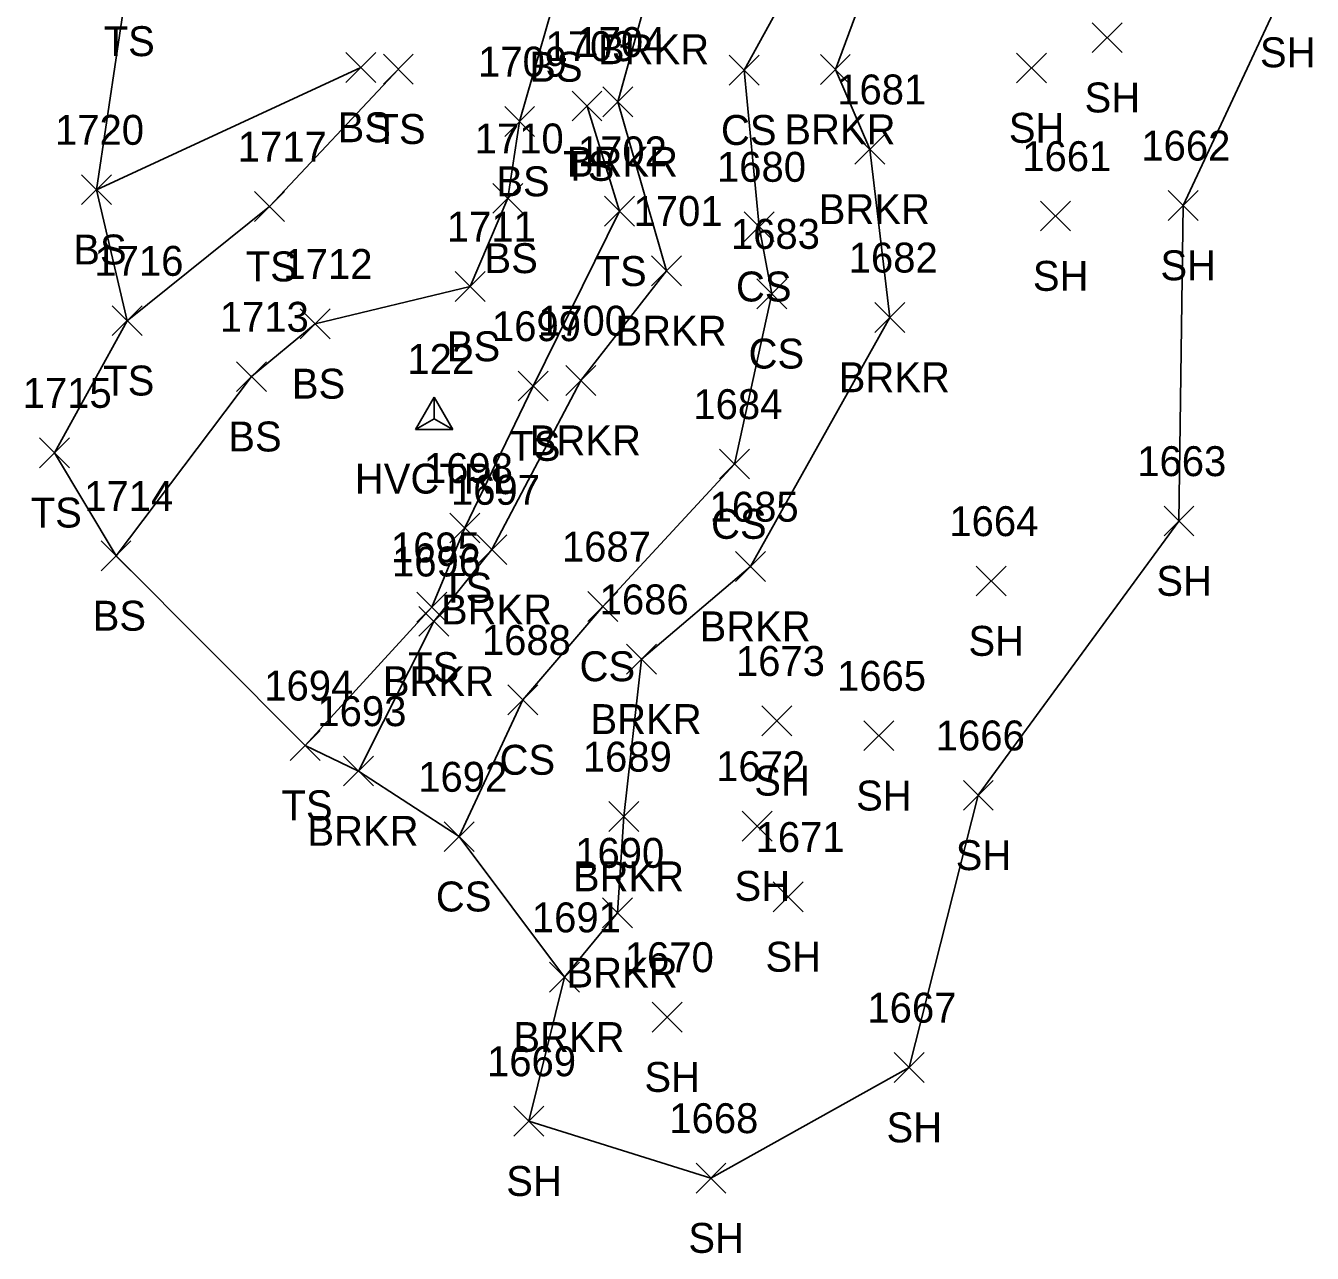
# Model space of a CAD drawing. Extents: x 1526508 to 1531550, y 369926 to 373082.
# Drawn here: x 1530980.2 to 1531066.1, y 369927.2 to 370009.2 of the extents above; entities that cross this region are included whole.
import ezdxf

# ---------------------------------------------------------------- set-up
doc = ezdxf.new("R2010")
doc.units = 0
for name, color, linetype in [('C_A', 7, 'Continuous'), ('C_I', 7, 'Continuous'), ('CPSM', 7, 'Continuous'), ('L_A', 7, 'Continuous'), ('L_I', 7, 'Continuous'), ('L_TIC', 7, 'Continuous'), ('LAWE', 7, 'Continuous'), ('LELB', 7, 'Continuous'), ('LSOGP', 7, 'Continuous')]:
    doc.layers.add(name, color=color, linetype=linetype)

msp = doc.modelspace()

# ---------------------------------------------------------------- linework, layer by layer
at = {"layer": 'CPSM'}
for p, q in [((1531006.222, 369982.223), (1531007.472, 369984.388)), ((1531008.722, 369982.223), (1531007.472, 369984.388)), ((1531007.473, 369982.944), (1531007.472, 369984.388)), ((1531006.222, 369982.223), (1531007.473, 369982.944)), ((1531007.473, 369982.944), (1531007.473, 369982.944)), ((1531007.473, 369982.944), (1531008.722, 369982.223)), ((1531006.222, 369982.223), (1531008.722, 369982.223))]:
    msp.add_line(p, q, dxfattribs=at)
at = {"layer": 'L_TIC'}
for points in [[(1531051.441, 370007.417), (1531053.441, 370009.417)], [(1531053.441, 370007.417), (1531051.441, 370009.417)], [(1531001.569, 370005.428), (1531003.569, 370007.428)], [(1531003.569, 370005.428), (1531001.569, 370007.428)], [(1531004.072, 370005.31), (1531006.072, 370007.31)], [(1531006.072, 370005.31), (1531004.072, 370007.31)], [(1531027.189, 370005.244), (1531029.189, 370007.244)], [(1531029.189, 370005.244), (1531027.189, 370007.244)], [(1531033.276, 370005.285), (1531035.276, 370007.285)], [(1531035.276, 370005.285), (1531033.276, 370007.285)], [(1531046.38, 370005.389), (1531048.38, 370007.389)], [(1531048.38, 370005.389), (1531046.38, 370007.389)], [(1531018.739, 370003.121), (1531020.739, 370005.121)], [(1531020.739, 370003.121), (1531018.739, 370005.121)], [(1531016.68, 370002.846), (1531018.68, 370004.846)], [(1531018.68, 370002.846), (1531016.68, 370004.846)], [(1531012.178, 370001.812), (1531014.178, 370003.812)], [(1531014.178, 370001.812), (1531012.178, 370003.812)], [(1531035.574, 369999.952), (1531037.574, 370001.952)], [(1531037.574, 369999.952), (1531035.574, 370001.952)], [(1530983.907, 369997.254), (1530985.907, 369999.254)], [(1530985.907, 369997.254), (1530983.907, 369999.254)], [(1531011.386, 369996.677), (1531013.386, 369998.677)], [(1531013.386, 369996.677), (1531011.386, 369998.677)], [(1531056.51, 369996.199), (1531058.51, 369998.199)], [(1531058.51, 369996.199), (1531056.51, 369998.199)], [(1530995.465, 369996.124), (1530997.465, 369998.124)], [(1530997.465, 369996.124), (1530995.465, 369998.124)], [(1531018.843, 369995.815), (1531020.843, 369997.815)], [(1531020.843, 369995.815), (1531018.843, 369997.815)], [(1531047.987, 369995.494), (1531049.987, 369997.494)], [(1531049.987, 369995.494), (1531047.987, 369997.494)], [(1531028.192, 369994.782), (1531030.192, 369996.782)], [(1531030.192, 369994.782), (1531028.192, 369996.782)], [(1531021.995, 369991.828), (1531023.995, 369993.828)], [(1531023.995, 369991.828), (1531021.995, 369993.828)], [(1531008.872, 369990.787), (1531010.872, 369992.787)], [(1531010.872, 369990.787), (1531008.872, 369992.787)], [(1531029.035, 369990.3), (1531031.035, 369992.3)], [(1531031.035, 369990.3), (1531029.035, 369992.3)], [(1530985.942, 369988.497), (1530987.942, 369990.497)], [(1530987.942, 369988.497), (1530985.942, 369990.497)], [(1531036.909, 369988.716), (1531038.909, 369990.716)], [(1531038.909, 369988.716), (1531036.909, 369990.716)], [(1530998.516, 369988.286), (1531000.516, 369990.286)], [(1531000.516, 369988.286), (1530998.516, 369990.286)], [(1530994.267, 369984.757), (1530996.267, 369986.757)], [(1530996.267, 369984.757), (1530994.267, 369986.757)], [(1531013.077, 369984.131), (1531015.077, 369986.131)], [(1531015.077, 369984.131), (1531013.077, 369986.131)], [(1531016.264, 369984.498), (1531018.264, 369986.498)], [(1531018.264, 369984.498), (1531016.264, 369986.498)], [(1530981.094, 369979.673), (1530983.094, 369981.673)], [(1530983.094, 369979.673), (1530981.094, 369981.673)], [(1531026.529, 369978.919), (1531028.529, 369980.919)], [(1531028.529, 369978.919), (1531026.529, 369980.919)], [(1531056.238, 369975.108), (1531058.238, 369977.108)], [(1531058.238, 369975.108), (1531056.238, 369977.108)], [(1531008.521, 369974.644), (1531010.521, 369976.644)], [(1531010.521, 369974.644), (1531008.521, 369976.644)], [(1531010.329, 369973.195), (1531012.329, 369975.195)], [(1531012.329, 369973.195), (1531010.329, 369975.195)], [(1530985.205, 369972.777), (1530987.205, 369974.777)], [(1530987.205, 369972.777), (1530985.205, 369974.777)], [(1531027.612, 369972.066), (1531029.612, 369974.066)], [(1531029.612, 369972.066), (1531027.612, 369974.066)], [(1531043.681, 369971.098), (1531045.681, 369973.098)], [(1531045.681, 369971.098), (1531043.681, 369973.098)], [(1531006.316, 369969.342), (1531008.316, 369971.342)], [(1531008.316, 369969.342), (1531006.316, 369971.342)], [(1531017.741, 369969.401), (1531019.741, 369971.401)], [(1531019.741, 369969.401), (1531017.741, 369971.401)], [(1531006.446, 369968.402), (1531008.446, 369970.402)], [(1531008.446, 369968.402), (1531006.446, 369970.402)], [(1531020.32, 369965.868), (1531022.32, 369967.868)], [(1531022.32, 369965.868), (1531020.32, 369967.868)], [(1531012.395, 369963.149), (1531014.395, 369965.149)], [(1531014.395, 369963.149), (1531012.395, 369965.149)], [(1531029.369, 369961.755), (1531031.369, 369963.755)], [(1531031.369, 369961.755), (1531029.369, 369963.755)], [(1530997.854, 369960.108), (1530999.854, 369962.108)], [(1530999.854, 369960.108), (1530997.854, 369962.108)], [(1531036.174, 369960.759), (1531038.174, 369962.759)], [(1531038.174, 369960.759), (1531036.174, 369962.759)], [(1531001.404, 369958.398), (1531003.404, 369960.398)], [(1531003.404, 369958.398), (1531001.404, 369960.398)], [(1531042.829, 369956.774), (1531044.829, 369958.774)], [(1531044.829, 369956.774), (1531042.829, 369958.774)], [(1531019.147, 369955.358), (1531021.147, 369957.358)], [(1531021.147, 369955.358), (1531019.147, 369957.358)], [(1531028.049, 369954.72), (1531030.049, 369956.72)], [(1531030.049, 369954.72), (1531028.049, 369956.72)], [(1531008.139, 369954.011), (1531010.139, 369956.011)], [(1531010.139, 369954.011), (1531008.139, 369956.011)], [(1531030.119, 369949.985), (1531032.119, 369951.985)], [(1531032.119, 369949.985), (1531030.119, 369951.985)], [(1531018.718, 369948.927), (1531020.718, 369950.927)], [(1531020.718, 369948.927), (1531018.718, 369950.927)], [(1531015.167, 369944.616), (1531017.167, 369946.616)], [(1531017.167, 369944.616), (1531015.167, 369946.616)], [(1531022.03, 369941.953), (1531024.03, 369943.953)], [(1531024.03, 369941.953), (1531022.03, 369943.953)], [(1531038.207, 369938.58), (1531040.207, 369940.58)], [(1531040.207, 369938.58), (1531038.207, 369940.58)], [(1531012.795, 369934.997), (1531014.795, 369936.997)], [(1531014.795, 369934.997), (1531012.795, 369936.997)], [(1531024.965, 369931.193), (1531026.965, 369933.193)], [(1531026.965, 369931.193), (1531024.965, 369933.193)]]:
    msp.add_lwpolyline(points, dxfattribs=at)
at = {"layer": 'LAWE'}
for points in [[(1531060.475, 370091.712), (1531052.156, 370080.261), (1531044.198, 370067.732), (1531036.367, 370062.528), (1531030.602, 370052.039), (1531024.354, 370038.592), (1531026.106, 370027.484), (1531033.741, 370021.245), (1531037.461, 370014.917), (1531034.276, 370006.285), (1531036.574, 370000.952), (1531037.909, 369989.716), (1531028.612, 369973.066), (1531021.32, 369966.868), (1531020.147, 369956.358), (1531019.718, 369949.927), (1531016.167, 369945.616)], [(1531002.404, 369959.398), (1531007.446, 369969.402), (1531011.329, 369974.195), (1531017.264, 369985.498), (1531022.995, 369992.828), (1531019.739, 370004.121), (1531021.821, 370011.641), (1531020.947, 370017.944), (1531021.134, 370021.146)]]:
    msp.add_lwpolyline(points, dxfattribs=at)
at = {"layer": 'LELB'}
for points in [[(1531052.195, 370093.898), (1531049.718, 370088.151), (1531047.993, 370081.349), (1531041.848, 370072.074), (1531040.413, 370069.701), (1531036.278, 370064.915), (1531029.752, 370054.384), (1531023.869, 370046.306), (1531022.036, 370040.527), (1531022.957, 370027.162), (1531029.889, 370020.999), (1531033.283, 370015.536), (1531028.189, 370006.244), (1531029.192, 369995.782), (1531030.035, 369991.3), (1531027.529, 369979.919), (1531018.741, 369970.401), (1531013.395, 369964.149), (1531009.139, 369955.011)], [(1531015.379, 370010.47), (1531013.178, 370002.812), (1531012.386, 369997.677), (1531009.872, 369991.787), (1530999.516, 369989.286), (1530995.267, 369985.757), (1530986.205, 369973.777)], [(1530982.094, 369980.673), (1530986.942, 369989.497), (1530996.465, 369997.124), (1531005.072, 370006.31)], [(1531002.569, 370006.428), (1530984.907, 369998.254)], [(1530998.854, 369961.108), (1531007.316, 369970.342), (1531009.521, 369975.644), (1531014.077, 369985.131), (1531019.843, 369996.815), (1531017.68, 370003.846)]]:
    msp.add_lwpolyline(points, dxfattribs=at)
at = {"layer": 'LSOGP'}
msp.add_lwpolyline([(1530986.97, 370012.18), (1530984.907, 369998.254), (1530986.942, 369989.497), (1530982.094, 369980.673), (1530986.205, 369973.777), (1530998.854, 369961.108), (1531002.404, 369959.398), (1531009.139, 369955.011), (1531016.167, 369945.616), (1531013.795, 369935.997), (1531025.965, 369932.193), (1531039.207, 369939.58), (1531043.829, 369957.774), (1531057.238, 369976.108), (1531057.51, 369997.199), (1531064.161, 370011.436)], dxfattribs=at)

# ---------------------------------------------------------------- texts
at = {"layer": 'C_A'}
msp.add_text('HVCTRL', height=2, dxfattribs=at).set_placement((1531002.166, 369977.944))
at = {"layer": 'C_I'}
msp.add_text('122', height=2, dxfattribs=at).set_placement((1531005.678, 369985.944))
at = {"layer": 'L_A'}
for s, p in [('TS', (1530985.379, 370007.18)), ('BRKR', (1531018.411, 370006.641)), ('SH', (1531062.649, 370006.436)), ('BS', (1531013.82, 370005.47)), ('SH', (1531050.929, 370003.417)), ('BS', (1531001.01, 370001.428)), ('TS', (1531003.481, 370001.31)), ('SH', (1531045.868, 370001.389)), ('CS', (1531026.63, 370001.244)), ('BRKR', (1531030.866, 370001.285)), ('TS', (1531016.089, 369998.846)), ('BRKR', (1531016.329, 369999.121)), ('BS', (1531011.619, 369997.812)), ('BRKR', (1531033.164, 369995.952)), ('BS', (1530983.348, 369993.254)), ('TS', (1530994.874, 369992.124)), ('BS', (1531010.827, 369992.677)), ('SH', (1531055.999, 369992.199)), ('TS', (1531018.252, 369991.815)), ('SH', (1531047.475, 369991.494)), ('CS', (1531027.633, 369990.782)), ('BRKR', (1531019.586, 369987.828)), ('BS', (1531008.313, 369986.787)), ('CS', (1531028.476, 369986.3)), ('TS', (1530985.351, 369984.497)), ('BS', (1530997.957, 369984.286)), ('BRKR', (1531034.499, 369984.716)), ('BS', (1530993.708, 369980.757)), ('TS', (1531012.486, 369980.131)), ('BRKR', (1531013.854, 369980.498)), ('TS', (1530980.504, 369975.673)), ('CS', (1531025.97, 369974.919)), ('TS', (1531007.93, 369970.644)), ('SH', (1531055.726, 369971.108)), ('BS', (1530984.646, 369968.777)), ('BRKR', (1531007.919, 369969.195)), ('BRKR', (1531025.202, 369968.066)), ('SH', (1531043.169, 369967.098)), ('TS', (1531005.725, 369965.342)), ('CS', (1531017.182, 369965.401)), ('BRKR', (1531004.036, 369964.402)), ('BRKR', (1531017.91, 369961.868)), ('CS', (1531011.835, 369959.149)), ('SH', (1531028.857, 369957.755)), ('SH', (1531035.662, 369956.759)), ('TS', (1530997.263, 369956.108)), ('BRKR', (1530998.994, 369954.398)), ('SH', (1531042.317, 369952.774)), ('BRKR', (1531016.737, 369951.358)), ('SH', (1531027.538, 369950.72)), ('CS', (1531007.58, 369950.011)), ('SH', (1531029.607, 369945.985)), ('BRKR', (1531016.308, 369944.927)), ('BRKR', (1531012.757, 369940.616)), ('SH', (1531021.518, 369937.953)), ('SH', (1531037.695, 369934.58)), ('SH', (1531012.283, 369930.997)), ('SH', (1531024.453, 369927.193))]:
    msp.add_text(s, height=2, dxfattribs=at).set_placement(p)
at = {"layer": 'L_I'}
for s, p in [('1703', (1531014.908, 370006.846)), ('1704', (1531016.967, 370007.121)), ('1709', (1531010.399, 370005.812)), ('1681', (1531034.4, 370003.952)), ('1720', (1530982.128, 370001.254)), ('1710', (1531010.174, 370000.677)), ('1717', (1530994.339, 370000.124)), ('1702', (1531017.071, 369999.815)), ('1662', (1531054.723, 370000.199)), ('1680', (1531026.365, 369998.782)), ('1661', (1531046.766, 369999.494)), ('1701', (1531020.791, 369995.828)), ('1711', (1531008.313, 369994.787)), ('1683', (1531027.295, 369994.3)), ('1682', (1531035.169, 369992.716)), ('1716', (1530984.761, 369992.497)), ('1712', (1530997.39, 369992.286)), ('1713', (1530993.141, 369988.757)), ('1700', (1531014.405, 369988.498)), ('1699', (1531011.329, 369988.131)), ('1715', (1530979.968, 369983.673)), ('1684', (1531024.789, 369982.919)), ('1663', (1531054.451, 369979.108)), ('1698', (1531006.78, 369978.644)), ('1714', (1530984.08, 369976.777)), ('1697', (1531008.588, 369977.195)), ('1685', (1531025.872, 369976.066)), ('1664', (1531041.894, 369975.098)), ('1695', (1531004.575, 369973.342)), ('1687', (1531016.001, 369973.401)), ('1696', (1531004.65, 369972.402)), ('1686', (1531018.524, 369969.868)), ('1688', (1531010.654, 369967.149)), ('1673', (1531027.629, 369965.755)), ('1665', (1531034.387, 369964.759)), ('1694', (1530996.114, 369964.108)), ('1693', (1530999.664, 369962.398)), ('1666', (1531040.986, 369960.774)), ('1689', (1531017.399, 369959.358)), ('1672', (1531026.309, 369958.72)), ('1692', (1531006.399, 369958.011)), ('1671', (1531028.946, 369953.985)), ('1690', (1531016.891, 369952.927)), ('1691', (1531013.994, 369948.616)), ('1670', (1531020.203, 369945.953)), ('1667', (1531036.419, 369942.58)), ('1669', (1531011, 369938.997)), ('1668', (1531023.178, 369935.193))]:
    msp.add_text(s, height=2, dxfattribs=at).set_placement(p)

doc.saveas('drawing.dxf')
